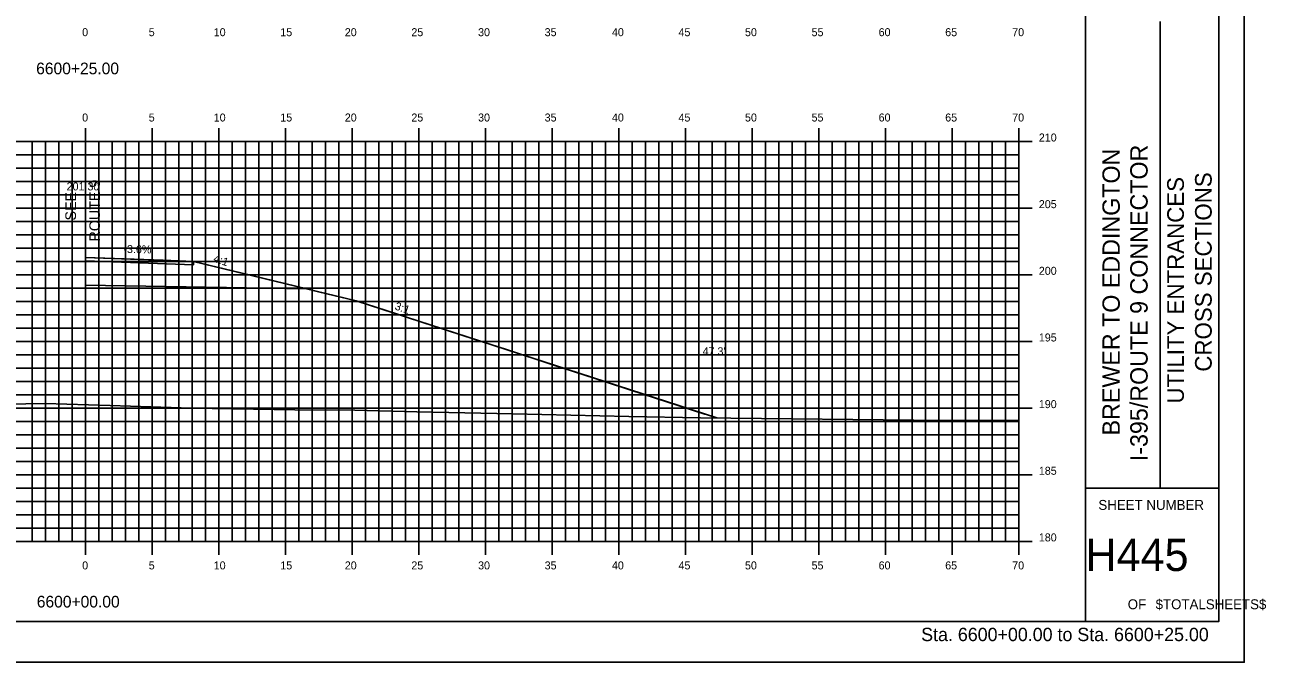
# Model space of a CAD drawing. Extents: x 1723074 to 1723246, y 459560 to 459670.
# Drawn here: x 1723152.9 to 1723246, y 459559.6 to 459607.4 of the extents above; entities that cross this region are included whole.
import ezdxf

# ---------------------------------------------------------------- set-up
doc = ezdxf.new("R2010")
doc.units = 0
for name, color, linetype in [('ANNOTATION', 7, 'Continuous'), ('BORDER', 7, 'Continuous'), ('D_Roadway_Centerline', 7, 'Continuous'), ('D_Roadway_Centerline_Text', 7, 'Continuous'), ('D_Roadway_Edge_Shoulder', 7, 'Continuous'), ('D_Roadway_Edge_TW', 7, 'Continuous'), ('D_Roadway_Pavement', 7, 'Continuous'), ('D_Roadway_SlopeLines', 7, 'Continuous'), ('D_Roadway_SubGrade', 7, 'Continuous'), ('D_Text_Standard', 7, 'Continuous'), ('H_V ANNOTATION', 7, 'Continuous'), ('HIGHWAY_TITLE', 7, 'Continuous'), ('MAJOR', 7, 'Continuous'), ('MINOR', 7, 'Continuous'), ('PLOT BOUNDARY', 7, 'Continuous'), ('S_Roadway_Centerline', 7, 'Continuous')]:
    doc.layers.add(name, color=color, linetype=linetype)

msp = doc.modelspace()

# ---------------------------------------------------------------- linework, layer by layer
at = {"layer": 'BORDER'}
for p, q in [((1723232.447, 459562.613), (1723232.447, 459667.613)), ((1723238.038, 459572.616), (1723238.038, 459607.616)), ((1723232.447, 459572.616), (1723242.447, 459572.616))]:
    msp.add_line(p, q, dxfattribs=at)
msp.add_lwpolyline([(1723082.447, 459562.613), (1723242.447, 459562.613), (1723242.447, 459667.613), (1723082.447, 459667.613)], close=True, dxfattribs=at)
at = {"layer": 'D_Roadway_Centerline'}
msp.add_lwpolyline([(1723157.447, 459589.914), (1723163.278, 459589.704), (1723165.567, 459589.622), (1723169.109, 459588.761), (1723174.055, 459587.56), (1723174.94, 459587.345), (1723177.748, 459586.663), (1723180.771, 459585.681), (1723181.598, 459585.412), (1723186.602, 459583.786), (1723189.027, 459582.998), (1723192.433, 459581.891), (1723196.461, 459580.582), (1723198.264, 459579.996), (1723203.903, 459578.164), (1723204.095, 459578.102), (1723204.79, 459577.876)], dxfattribs=at)
at = {"layer": 'D_Roadway_Edge_Shoulder'}
msp.add_lwpolyline([(1723157.447, 459589.914), (1723165.567, 459589.622), (1723165.567, 459589.372), (1723157.447, 459589.664)], close=True, dxfattribs=at)
msp.add_lwpolyline([(1723157.447, 459589.914), (1723165.567, 459589.622), (1723165.567, 459589.372), (1723157.447, 459589.664)], close=True, dxfattribs=at)
at = {"layer": 'D_Roadway_Edge_TW'}
msp.add_line((1723157.447, 459589.914), (1723157.447, 459589.664), dxfattribs=at)
msp.add_line((1723157.447, 459589.914), (1723157.447, 459589.664), dxfattribs=at)
msp.add_line((1723157.447, 459589.914), (1723157.447, 459589.664), dxfattribs=at)
at = {"layer": 'D_Roadway_Pavement'}
msp.add_line((1723157.447, 459589.664), (1723157.447, 459589.247), dxfattribs=at)
msp.add_line((1723157.447, 459589.664), (1723157.447, 459589.247), dxfattribs=at)
msp.add_lwpolyline([(1723157.447, 459589.664), (1723157.447, 459589.247)], dxfattribs=at)
at = {"layer": 'D_Roadway_SlopeLines'}
for points in [[(1723157.447, 459589.913), (1723157.447, 459588.913)], [(1723165.567, 459589.622), (1723177.748, 459586.663), (1723204.79, 459577.876)], [(1723165.567, 459589.622), (1723177.748, 459586.663), (1723204.79, 459577.876)], [(1723165.567, 459589.622), (1723177.748, 459586.663), (1723204.79, 459577.876)], [(1723165.567, 459589.622), (1723177.748, 459586.663), (1723204.79, 459577.876)], [(1723165.567, 459589.622), (1723177.748, 459586.663), (1723204.79, 459577.876)], [(1723165.567, 459589.622), (1723177.748, 459586.663), (1723204.79, 459577.876)], [(1723165.567, 459589.622), (1723177.748, 459586.663), (1723204.79, 459577.876)]]:
    msp.add_lwpolyline(points, dxfattribs=at)
at = {"layer": 'D_Roadway_SubGrade'}
for p in [(1723157.447, 459598.613), (1723157.447, 459589.664)]:
    msp.add_line(p, (1723157.447, 459587.83), dxfattribs=at)
for points in [[(1723157.447, 459589.247), (1723157.447, 459589.664), (1723165.567, 459589.372), (1723165.567, 459589.622), (1723174.055, 459587.56), (1723157.447, 459587.83)], [(1723157.447, 459589.664), (1723165.567, 459589.372), (1723165.567, 459589.622), (1723174.055, 459587.56), (1723157.447, 459587.83)]]:
    msp.add_lwpolyline(points, close=True, dxfattribs=at)
for points in [[(1723157.447, 459589.664), (1723165.567, 459589.372), (1723165.567, 459589.622), (1723174.055, 459587.56), (1723157.447, 459587.83)], [(1723157.447, 459589.664), (1723165.567, 459589.372), (1723165.567, 459589.622), (1723174.055, 459587.56), (1723157.447, 459587.83)], [(1723157.447, 459589.247), (1723157.447, 459589.664), (1723157.447, 459587.83)]]:
    msp.add_lwpolyline(points, dxfattribs=at)
at = {"layer": 'MAJOR'}
for p, q in [((1723157.447, 459599.615), (1723157.447, 459598.613)), ((1723162.447, 459599.615), (1723162.447, 459598.613)), ((1723167.447, 459599.615), (1723167.447, 459598.613)), ((1723172.447, 459599.615), (1723172.447, 459598.613)), ((1723177.447, 459599.615), (1723177.447, 459598.613)), ((1723182.447, 459599.615), (1723182.447, 459598.613)), ((1723187.447, 459599.615), (1723187.447, 459598.613)), ((1723192.447, 459599.615), (1723192.447, 459598.613)), ((1723197.447, 459599.615), (1723197.447, 459598.613)), ((1723202.447, 459599.615), (1723202.447, 459598.613)), ((1723207.447, 459599.615), (1723207.447, 459598.613)), ((1723212.447, 459599.615), (1723212.447, 459598.613)), ((1723217.447, 459599.615), (1723217.447, 459598.613)), ((1723222.447, 459599.615), (1723222.447, 459598.613)), ((1723227.447, 459599.615), (1723227.447, 459598.613)), ((1723087.447, 459598.613), (1723227.447, 459598.613)), ((1723087.447, 459598.613), (1723227.447, 459598.613)), ((1723157.447, 459568.613), (1723157.447, 459598.613)), ((1723162.447, 459568.613), (1723162.447, 459598.613)), ((1723167.447, 459568.613), (1723167.447, 459598.613)), ((1723172.447, 459568.613), (1723172.447, 459598.613)), ((1723177.447, 459568.613), (1723177.447, 459598.613)), ((1723182.447, 459568.613), (1723182.447, 459598.613)), ((1723187.447, 459568.613), (1723187.447, 459598.613)), ((1723192.447, 459568.613), (1723192.447, 459598.613)), ((1723197.447, 459568.613), (1723197.447, 459598.613)), ((1723202.447, 459568.613), (1723202.447, 459598.613)), ((1723207.447, 459568.613), (1723207.447, 459598.613)), ((1723212.447, 459568.613), (1723212.447, 459598.613)), ((1723217.447, 459568.613), (1723217.447, 459598.613)), ((1723222.447, 459568.613), (1723222.447, 459598.613)), ((1723228.449, 459598.613), (1723226.445, 459598.613)), ((1723227.447, 459568.613), (1723227.447, 459598.613)), ((1723227.447, 459568.613), (1723227.447, 459598.613)), ((1723087.447, 459593.613), (1723227.447, 459593.613)), ((1723228.449, 459593.613), (1723226.445, 459593.613)), ((1723087.447, 459588.613), (1723227.447, 459588.613)), ((1723228.449, 459588.613), (1723226.445, 459588.613)), ((1723087.447, 459583.613), (1723227.447, 459583.613)), ((1723228.449, 459583.613), (1723226.445, 459583.613)), ((1723087.447, 459578.613), (1723227.447, 459578.613)), ((1723228.449, 459578.613), (1723226.445, 459578.613)), ((1723087.447, 459573.613), (1723227.447, 459573.613)), ((1723228.449, 459573.613), (1723226.445, 459573.613)), ((1723087.447, 459568.613), (1723227.447, 459568.613)), ((1723087.447, 459568.613), (1723227.447, 459568.613)), ((1723157.447, 459567.611), (1723157.447, 459568.613)), ((1723162.447, 459567.611), (1723162.447, 459568.613)), ((1723167.447, 459567.611), (1723167.447, 459568.613)), ((1723172.447, 459567.611), (1723172.447, 459568.613)), ((1723177.447, 459567.611), (1723177.447, 459568.613)), ((1723182.447, 459567.611), (1723182.447, 459568.613)), ((1723187.447, 459567.611), (1723187.447, 459568.613)), ((1723192.447, 459567.611), (1723192.447, 459568.613)), ((1723197.447, 459567.611), (1723197.447, 459568.613)), ((1723202.447, 459567.611), (1723202.447, 459568.613)), ((1723207.447, 459567.611), (1723207.447, 459568.613)), ((1723212.447, 459567.611), (1723212.447, 459568.613)), ((1723217.447, 459567.611), (1723217.447, 459568.613)), ((1723222.447, 459567.611), (1723222.447, 459568.613)), ((1723228.449, 459568.613), (1723226.445, 459568.613)), ((1723227.447, 459567.611), (1723227.447, 459568.613))]:
    msp.add_line(p, q, dxfattribs=at)
at = {"layer": 'MINOR'}
for p, q in [((1723153.447, 459568.613), (1723153.447, 459598.613)), ((1723154.447, 459568.613), (1723154.447, 459598.613)), ((1723155.447, 459568.613), (1723155.447, 459598.613)), ((1723156.447, 459568.613), (1723156.447, 459598.613)), ((1723158.447, 459568.613), (1723158.447, 459598.613)), ((1723159.447, 459568.613), (1723159.447, 459598.613)), ((1723160.447, 459568.613), (1723160.447, 459598.613)), ((1723161.447, 459568.613), (1723161.447, 459598.613)), ((1723163.447, 459568.613), (1723163.447, 459598.613)), ((1723164.447, 459568.613), (1723164.447, 459598.613)), ((1723165.447, 459568.613), (1723165.447, 459598.613)), ((1723166.447, 459568.613), (1723166.447, 459598.613)), ((1723168.447, 459568.613), (1723168.447, 459598.613)), ((1723169.447, 459568.613), (1723169.447, 459598.613)), ((1723170.447, 459568.613), (1723170.447, 459598.613)), ((1723171.447, 459568.613), (1723171.447, 459598.613)), ((1723173.447, 459568.613), (1723173.447, 459598.613)), ((1723174.447, 459568.613), (1723174.447, 459598.613)), ((1723175.447, 459568.613), (1723175.447, 459598.613)), ((1723176.447, 459568.613), (1723176.447, 459598.613)), ((1723178.447, 459568.613), (1723178.447, 459598.613)), ((1723179.447, 459568.613), (1723179.447, 459598.613)), ((1723180.447, 459568.613), (1723180.447, 459598.613)), ((1723181.447, 459568.613), (1723181.447, 459598.613)), ((1723183.447, 459568.613), (1723183.447, 459598.613)), ((1723184.447, 459568.613), (1723184.447, 459598.613)), ((1723185.447, 459568.613), (1723185.447, 459598.613)), ((1723186.447, 459568.613), (1723186.447, 459598.613)), ((1723188.447, 459568.613), (1723188.447, 459598.613)), ((1723189.447, 459568.613), (1723189.447, 459598.613)), ((1723190.447, 459568.613), (1723190.447, 459598.613)), ((1723191.447, 459568.613), (1723191.447, 459598.613)), ((1723193.447, 459568.613), (1723193.447, 459598.613)), ((1723194.447, 459568.613), (1723194.447, 459598.613)), ((1723195.447, 459568.613), (1723195.447, 459598.613)), ((1723196.447, 459568.613), (1723196.447, 459598.613)), ((1723198.447, 459568.613), (1723198.447, 459598.613)), ((1723199.447, 459568.613), (1723199.447, 459598.613)), ((1723200.447, 459568.613), (1723200.447, 459598.613)), ((1723201.447, 459568.613), (1723201.447, 459598.613)), ((1723203.447, 459568.613), (1723203.447, 459598.613)), ((1723204.447, 459568.613), (1723204.447, 459598.613)), ((1723205.447, 459568.613), (1723205.447, 459598.613)), ((1723206.447, 459568.613), (1723206.447, 459598.613)), ((1723208.447, 459568.613), (1723208.447, 459598.613)), ((1723209.447, 459568.613), (1723209.447, 459598.613)), ((1723210.447, 459568.613), (1723210.447, 459598.613)), ((1723211.447, 459568.613), (1723211.447, 459598.613)), ((1723213.447, 459568.613), (1723213.447, 459598.613)), ((1723214.447, 459568.613), (1723214.447, 459598.613)), ((1723215.447, 459568.613), (1723215.447, 459598.613)), ((1723216.447, 459568.613), (1723216.447, 459598.613)), ((1723218.447, 459568.613), (1723218.447, 459598.613)), ((1723219.447, 459568.613), (1723219.447, 459598.613)), ((1723220.447, 459568.613), (1723220.447, 459598.613)), ((1723221.447, 459568.613), (1723221.447, 459598.613)), ((1723223.447, 459568.613), (1723223.447, 459598.613)), ((1723224.447, 459568.613), (1723224.447, 459598.613)), ((1723225.447, 459568.613), (1723225.447, 459598.613)), ((1723226.447, 459568.613), (1723226.447, 459598.613)), ((1723087.447, 459597.613), (1723227.447, 459597.613)), ((1723227.447, 459597.613), (1723226.445, 459597.613)), ((1723087.447, 459596.613), (1723227.447, 459596.613)), ((1723227.447, 459596.613), (1723226.445, 459596.613)), ((1723087.447, 459595.613), (1723227.447, 459595.613)), ((1723227.447, 459595.613), (1723226.445, 459595.613)), ((1723087.447, 459594.613), (1723227.447, 459594.613)), ((1723227.447, 459594.613), (1723226.445, 459594.613)), ((1723087.447, 459592.613), (1723227.447, 459592.613)), ((1723227.447, 459592.613), (1723226.445, 459592.613)), ((1723087.447, 459591.613), (1723227.447, 459591.613)), ((1723227.447, 459591.613), (1723226.445, 459591.613)), ((1723087.447, 459590.613), (1723227.447, 459590.613)), ((1723227.447, 459590.613), (1723226.445, 459590.613)), ((1723087.447, 459589.613), (1723227.447, 459589.613)), ((1723227.447, 459589.613), (1723226.445, 459589.613)), ((1723087.447, 459587.613), (1723227.447, 459587.613)), ((1723227.447, 459587.613), (1723226.445, 459587.613)), ((1723087.447, 459586.613), (1723227.447, 459586.613)), ((1723227.447, 459586.613), (1723226.445, 459586.613)), ((1723087.447, 459585.613), (1723227.447, 459585.613)), ((1723227.447, 459585.613), (1723226.445, 459585.613)), ((1723087.447, 459584.613), (1723227.447, 459584.613)), ((1723227.447, 459584.613), (1723226.445, 459584.613)), ((1723087.447, 459582.613), (1723227.447, 459582.613)), ((1723227.447, 459582.613), (1723226.445, 459582.613)), ((1723087.447, 459581.613), (1723227.447, 459581.613)), ((1723227.447, 459581.613), (1723226.445, 459581.613)), ((1723087.447, 459580.613), (1723227.447, 459580.613)), ((1723227.447, 459580.613), (1723226.445, 459580.613)), ((1723087.447, 459579.613), (1723227.447, 459579.613)), ((1723227.447, 459579.613), (1723226.445, 459579.613)), ((1723087.447, 459577.613), (1723227.447, 459577.613)), ((1723227.447, 459577.613), (1723226.445, 459577.613)), ((1723087.447, 459576.613), (1723227.447, 459576.613)), ((1723227.447, 459576.613), (1723226.445, 459576.613)), ((1723087.447, 459575.613), (1723227.447, 459575.613)), ((1723227.447, 459575.613), (1723226.445, 459575.613)), ((1723087.447, 459574.613), (1723227.447, 459574.613)), ((1723227.447, 459574.613), (1723226.445, 459574.613)), ((1723087.447, 459572.613), (1723227.447, 459572.613)), ((1723227.447, 459572.613), (1723226.445, 459572.613)), ((1723087.447, 459571.613), (1723227.447, 459571.613)), ((1723227.447, 459571.613), (1723226.445, 459571.613)), ((1723087.447, 459570.613), (1723227.447, 459570.613)), ((1723227.447, 459570.613), (1723226.445, 459570.613)), ((1723087.447, 459569.613), (1723227.447, 459569.613)), ((1723227.447, 459569.613), (1723226.445, 459569.613))]:
    msp.add_line(p, q, dxfattribs=at)
at = {"layer": 'PLOT BOUNDARY'}
msp.add_lwpolyline([(1723074.354, 459559.554), (1723244.354, 459559.554), (1723244.354, 459669.554), (1723074.354, 459669.554)], close=True, dxfattribs=at)
at = {"layer": 'S_Roadway_Centerline'}
msp.add_lwpolyline([(1723087.447, 459580.369), (1723094.068, 459580.232), (1723096.872, 459580.127), (1723107.413, 459579.621), (1723116.973, 459579.673), (1723119.736, 459579.697), (1723136.461, 459578.751), (1723141.891, 459578.708), (1723148.625, 459578.862), (1723154.423, 459578.971), (1723159.303, 459578.809), (1723165.405, 459578.604), (1723173.145, 459578.488), (1723177.65, 459578.448), (1723182.291, 459578.322), (1723189.491, 459578.187), (1723198.21, 459577.983), (1723203.587, 459577.889), (1723221.841, 459577.683), (1723222.678, 459577.682), (1723223.436, 459577.685), (1723227.447, 459577.702)], dxfattribs=at)

# ---------------------------------------------------------------- texts
at = {"layer": 'ANNOTATION'}
for s, height, rotation, p in [('ROUTE 9', 0.8, 90, (1723158.545, 459591.112)), ('SEE', 0.8, 90, (1723156.745, 459592.687)), ('-3.6%', 0.6, 358.85424, (1723160.295, 459590.256)), ('4:1', 0.6, 341.56505, (1723167, 459589.598)), ('3:1', 0.6, 341.56505, (1723180.601, 459586.024))]:
    msp.add_text(s, height=height, rotation=rotation, dxfattribs=at).set_placement(p)
at = {"layer": 'BORDER'}
for s, p in [('UTILITY ENTRANCES', (1723239.824, 459578.955)), ('CROSS SECTIONS', (1723241.911, 459581.347))]:
    msp.add_text(s, height=1.25, rotation=90, dxfattribs=at).set_placement(p)
for s, height, p in [('SHEET NUMBER', 0.74527, (1723233.413, 459570.979)), ('H445', 2.4194, (1723232.438, 459566.395)), ('OF', 0.7453, (1723235.614, 459563.526)), ('$TOTALSHEETS$', 0.74527, (1723237.704, 459563.526))]:
    msp.add_text(s, height=height, dxfattribs=at).set_placement(p)
at = {"layer": 'D_Roadway_Centerline_Text'}
msp.add_text('201.30', height=0.6, dxfattribs=at).set_placement((1723156.04, 459594.945))
at = {"layer": 'D_Text_Standard'}
msp.add_text("47.3'", height=0.6, dxfattribs=at).set_placement((1723203.733, 459582.576))
at = {"layer": 'H_V ANNOTATION'}
for s, height, p in [('0', 0.6, (1723157.206, 459606.513)), ('5', 0.6, (1723162.198, 459606.513)), ('10', 0.6, (1723167.072, 459606.513)), ('15', 0.6, (1723172.064, 459606.513)), ('20', 0.6, (1723176.901, 459606.513)), ('25', 0.6, (1723181.893, 459606.513)), ('30', 0.6, (1723186.896, 459606.513)), ('35', 0.6, (1723191.888, 459606.513)), ('40', 0.6, (1723196.933, 459606.513)), ('45', 0.6, (1723201.925, 459606.513)), ('50', 0.6, (1723206.912, 459606.513)), ('55', 0.6, (1723211.904, 459606.513)), ('60', 0.6, (1723216.933, 459606.513)), ('65', 0.6, (1723221.925, 459606.513)), ('70', 0.6, (1723226.949, 459606.513)), ('6600+25.00', 0.875, (1723153.756, 459603.656)), ('0', 0.6, (1723157.206, 459600.113)), ('5', 0.6, (1723162.198, 459600.113)), ('10', 0.6, (1723167.072, 459600.113)), ('15', 0.6, (1723172.064, 459600.113)), ('20', 0.6, (1723176.901, 459600.113)), ('25', 0.6, (1723181.893, 459600.113)), ('30', 0.6, (1723186.896, 459600.113)), ('35', 0.6, (1723191.888, 459600.113)), ('40', 0.6, (1723196.933, 459600.113)), ('45', 0.6, (1723201.925, 459600.113)), ('50', 0.6, (1723206.912, 459600.113)), ('55', 0.6, (1723211.904, 459600.113)), ('60', 0.6, (1723216.933, 459600.113)), ('65', 0.6, (1723221.925, 459600.113)), ('70', 0.6, (1723226.949, 459600.113)), ('210', 0.6, (1723228.947, 459598.613)), ('205', 0.6, (1723228.947, 459593.613)), ('200', 0.6, (1723228.947, 459588.613)), ('195', 0.6, (1723228.947, 459583.613)), ('190', 0.6, (1723228.947, 459578.613)), ('185', 0.6, (1723228.947, 459573.613)), ('180', 0.6, (1723228.947, 459568.613)), ('0', 0.6, (1723157.206, 459566.513)), ('5', 0.6, (1723162.198, 459566.513)), ('10', 0.6, (1723167.072, 459566.513)), ('15', 0.6, (1723172.064, 459566.513)), ('20', 0.6, (1723176.901, 459566.513)), ('25', 0.6, (1723181.893, 459566.513)), ('30', 0.6, (1723186.896, 459566.513)), ('35', 0.6, (1723191.888, 459566.513)), ('40', 0.6, (1723196.933, 459566.513)), ('45', 0.6, (1723201.925, 459566.513)), ('50', 0.6, (1723206.912, 459566.513)), ('55', 0.6, (1723211.904, 459566.513)), ('60', 0.6, (1723216.933, 459566.513)), ('65', 0.6, (1723221.925, 459566.513)), ('70', 0.6, (1723226.949, 459566.513)), ('6600+00.00', 0.875, (1723153.803, 459563.656)), ('Sta. 6600+00.00 to Sta. 6600+25.00', 1.0002, (1723220.123, 459561.133))]:
    msp.add_text(s, height=height, dxfattribs=at).set_placement(p)
at = {"layer": 'HIGHWAY_TITLE'}
for s, p in [('I-395/ROUTE 9 CONNECTOR', (1723237.106, 459574.631)), ('BREWER TO EDDINGTON', (1723235.02, 459576.564))]:
    msp.add_text(s, height=1.30428, rotation=90, dxfattribs=at).set_placement(p)

doc.saveas('drawing.dxf')
